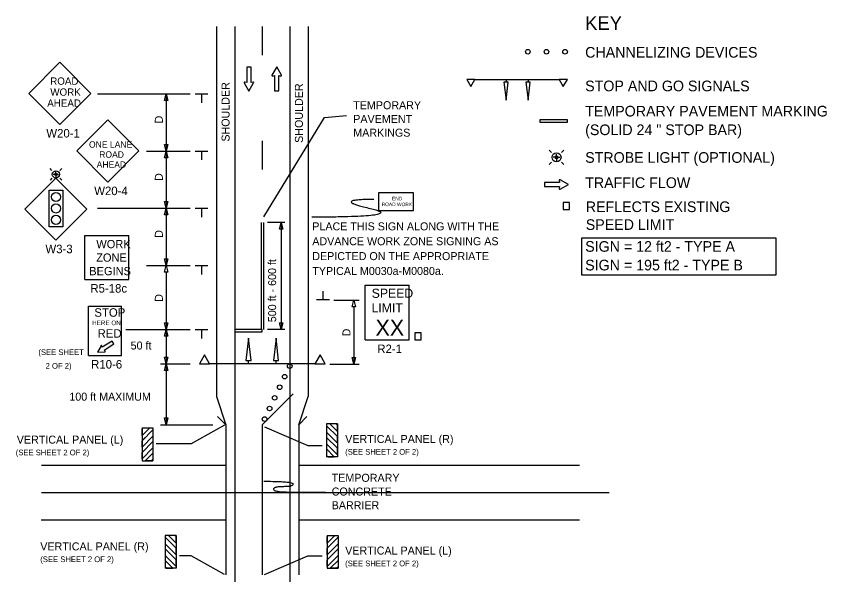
# Model space of a CAD drawing. Extents: x 16733 to 18484, y 7218 to 8208.
# Drawn here: x 16739 to 17447, y 7706 to 8195 of the extents above; entities that cross this region are included whole.
import ezdxf

# ---------------------------------------------------------------- set-up
doc = ezdxf.new("R2010")
doc.units = 0
for name, color, linetype in [('ALI_LEGAL_EX', 7, 'Continuous'), ('MT_SCRATCH_LEVEL_E', 7, 'Continuous'), ('PAVT_EDGE_EX', 7, 'Continuous'), ('TRAFFIC_SIGNS_PR', 7, 'Continuous'), ('TYPICAL_TEXT_DIMEN_EX', 7, 'Continuous'), ('TYPICAL_TEXT_DIMEN_PR', 7, 'Continuous')]:
    doc.layers.add(name, color=color, linetype=linetype)

msp = doc.modelspace()

# ---------------------------------------------------------------- linework, layer by layer
at = {"layer": 'ALI_LEGAL_EX'}
for points in [[(16953.78, 8185.68), (16953.78, 8160.68)], [(16953.78, 8085.68), (16953.78, 8060.68)], [(16952.78, 8014.45), (16952.78, 7920.82)], [(16954.78, 8014.45), (16954.78, 7920.82)]]:
    msp.add_lwpolyline(points, dxfattribs=at)
at = {"layer": 'MT_SCRATCH_LEVEL_E'}
for p, q in [((16943.98, 8150.09), (16940.24, 8150.09)), ((16940.24, 8150.09), (16940.24, 8136.83)), ((16943.98, 8150.09), (16940.24, 8150.09)), ((16940.24, 8150.09), (16940.24, 8136.83)), ((16943.98, 8136.83), (16943.98, 8150.09)), ((16943.98, 8136.83), (16943.98, 8150.09)), ((16966.37, 8150.35), (16962.26, 8143.11)), ((16966.37, 8150.35), (16962.26, 8143.11)), ((16970.52, 8143.11), (16966.37, 8150.35)), ((16970.52, 8143.11), (16966.37, 8150.35)), ((16962.74, 8142.43), (16964.52, 8142.74)), ((16962.74, 8142.43), (16964.52, 8142.74)), ((16964.52, 8142.74), (16964.52, 8129.49)), ((16964.52, 8142.74), (16964.52, 8129.49)), ((16968.26, 8129.49), (16968.26, 8142.74)), ((16968.26, 8142.74), (16970.04, 8142.43)), ((16968.26, 8129.49), (16968.26, 8142.74)), ((16968.26, 8142.74), (16970.04, 8142.43)), ((16937.98, 8136.47), (16942.13, 8129.22)), ((16937.98, 8136.47), (16942.13, 8129.22)), ((16940.24, 8136.83), (16938.46, 8137.15)), ((16940.24, 8136.83), (16938.46, 8137.15)), ((16942.13, 8129.22), (16946.24, 8136.47)), ((16942.13, 8129.22), (16946.24, 8136.47)), ((16945.76, 8137.15), (16943.98, 8136.83)), ((16945.76, 8137.15), (16943.98, 8136.83)), ((16964.52, 8129.49), (16968.26, 8129.49)), ((16964.52, 8129.49), (16968.26, 8129.49)), ((17213.71, 8049.47), (17200.46, 8049.47)), ((17200.46, 8049.47), (17200.46, 8045.73)), ((17213.71, 8049.47), (17200.46, 8049.47)), ((17200.46, 8049.47), (17200.46, 8045.73)), ((17213.4, 8051.25), (17213.71, 8049.47)), ((17213.4, 8051.25), (17213.71, 8049.47)), ((17221.32, 8047.62), (17214.08, 8051.73)), ((17221.32, 8047.62), (17214.08, 8051.73)), ((17200.46, 8045.73), (17213.71, 8045.73)), ((17200.46, 8045.73), (17213.71, 8045.73)), ((17213.71, 8045.73), (17213.4, 8043.95)), ((17213.71, 8045.73), (17213.4, 8043.95)), ((17214.08, 8043.48), (17221.32, 8047.62)), ((17214.08, 8043.48), (17221.32, 8047.62))]:
    msp.add_line(p, q, dxfattribs=at)
for centre, start, end in [((16962.67, 8142.89), 150.42484, 279.96381), ((16962.67, 8142.89), 150.42484, 279.96381), ((16970.11, 8142.89), 260.03619, 29.77312), ((16970.11, 8142.89), 260.03619, 29.77312), ((16938.39, 8136.69), 80.03619, 209.77312), ((16938.39, 8136.69), 80.03619, 209.77312), ((16945.83, 8136.69), 330.42484, 99.96381), ((16945.83, 8136.69), 330.42484, 99.96381), ((17213.86, 8051.33), 60.42484, 189.96381), ((17213.86, 8051.33), 60.42484, 189.96381), ((17213.86, 8043.88), 170.03619, 299.77312), ((17213.86, 8043.88), 170.03619, 299.77312)]:
    msp.add_arc(centre, 0.463, start, end, dxfattribs=at)
at = {"layer": 'PAVT_EDGE_EX'}
for p, q in [((16913.78, 8185.68), (16913.78, 7862.31)), ((16929.78, 8185.68), (16929.78, 7363.75)), ((16977.78, 8185.68), (16977.78, 7363.75)), ((16993.78, 8185.68), (16993.78, 7862.31)), ((16913.78, 7862.31), (16921.78, 7837.6)), ((16953.78, 7837.6), (16980.8, 7864.62)), ((16985.78, 7837.6), (16993.78, 7862.31)), ((16921.78, 7837.6), (16914.71, 7844.68)), ((16985.78, 7837.6), (16992.85, 7844.68)), ((16921.78, 7837.6), (16921.78, 7706.21)), ((16953.78, 7837.6), (16953.78, 7706.21)), ((16985.78, 7837.6), (16985.78, 7706.21)), ((16760.93, 7802.34), (16921.78, 7802.34)), ((16985.78, 7802.34), (17230.97, 7802.34)), ((16760.93, 7778.34), (17256.97, 7778.34)), ((16760.41, 7754.34), (16921.78, 7754.34)), ((16985.78, 7754.34), (17230.97, 7754.34))]:
    msp.add_line(p, q, dxfattribs=at)
for points in [[(16760.93, 7778.34), (16785.93, 7778.34)], [(16860.93, 7778.34), (16885.93, 7778.34)], [(17060.93, 7778.34), (17085.93, 7778.34)], [(17160.93, 7778.34), (17185.93, 7778.34)]]:
    msp.add_lwpolyline(points, dxfattribs=at)
at = {"layer": 'TRAFFIC_SIGNS_PR'}
for p, q in [((16776.85, 8154.4), (16749.69, 8127.25)), ((16804, 8127.25), (16776.85, 8154.4)), ((17139.67, 8139.38), (17213.27, 8139.38)), ((17166.87, 8139.38), (17166.87, 8136.97)), ((17186.07, 8139.38), (17186.07, 8136.97)), ((16749.69, 8127.25), (16776.85, 8100.09)), ((16776.85, 8100.09), (16804, 8127.25)), ((16818.71, 8104.04), (16791.55, 8076.89)), ((16845.86, 8076.89), (16818.71, 8104.04)), ((17206.69, 8075.61), (17204.66, 8077.65)), ((17215.25, 8075.61), (17217.29, 8077.65)), ((16791.55, 8076.89), (16818.71, 8049.73)), ((16818.71, 8049.73), (16845.86, 8076.89)), ((17210.97, 8071.33), (17208.1, 8071.33)), ((17210.97, 8071.33), (17210.97, 8074.21)), ((17210.97, 8071.33), (17210.97, 8067.4)), ((17210.97, 8071.33), (17213.85, 8071.33)), ((17206.69, 8067.05), (17204.66, 8065.02)), ((17217.29, 8065.02), (17215.25, 8067.05)), ((16769.94, 8059.84), (16768.32, 8061.46)), ((16773.37, 8056.41), (16771.07, 8056.41)), ((16773.37, 8056.41), (16773.37, 8058.72)), ((16773.37, 8056.41), (16773.37, 8053.26)), ((16773.37, 8056.41), (16775.67, 8056.41)), ((16776.79, 8059.84), (16778.42, 8061.46)), ((16773.37, 8053.26), (16746.22, 8026.11)), ((16769.94, 8052.99), (16768.32, 8051.36)), ((16800.52, 8026.11), (16773.37, 8053.26)), ((16778.42, 8051.36), (16776.79, 8052.99)), ((16746.22, 8026.11), (16773.37, 7998.96)), ((16773.37, 7998.96), (16800.52, 8026.11)), ((16798.7, 7964.51), (16798.7, 8002.91)), ((16798.7, 8002.91), (16837.1, 8002.91)), ((16837.1, 7964.51), (16837.1, 8002.91)), ((16798.7, 7964.51), (16837.1, 7964.51)), ((17043.66, 7959.64), (17082.06, 7959.64)), ((17043.66, 7911.64), (17043.66, 7959.64)), ((17082.06, 7911.64), (17082.06, 7959.64)), ((16801.79, 7941.3), (16830.59, 7941.3)), ((16801.79, 7898.1), (16801.79, 7941.3)), ((16816.19, 7941.3), (16816.19, 7941.3)), ((16830.59, 7898.1), (16830.59, 7941.3)), ((17043.66, 7911.64), (17082.06, 7911.64)), ((16801.79, 7898.1), (16830.59, 7898.1)), ((16941.78, 7890.82), (16941.78, 7893.84)), ((16965.78, 7890.82), (16965.78, 7893.84)), ((16999.78, 7890.82), (16907.78, 7890.82)), ((17019.53, 7838.39), (17009.93, 7838.39)), ((17009.93, 7838.39), (17009.93, 7809.59)), ((17019.53, 7827.12), (17009.93, 7836.72)), ((17019.53, 7831.64), (17012.78, 7838.39)), ((17019.53, 7837.3), (17018.44, 7838.39)), ((17019.53, 7838.39), (17019.53, 7809.59)), ((16848.65, 7834.79), (16858.25, 7834.79)), ((16848.65, 7834.79), (16848.65, 7805.99)), ((16848.65, 7833.71), (16849.74, 7834.79)), ((16848.65, 7828.05), (16855.4, 7834.79)), ((16848.65, 7823.52), (16858.25, 7833.12)), ((16858.25, 7834.79), (16858.25, 7805.99)), ((17019.53, 7821.46), (17009.93, 7831.06)), ((16848.65, 7817.87), (16858.25, 7827.47)), ((16848.65, 7813.34), (16858.25, 7822.94)), ((16850.07, 7824.94), (16851.48, 7826.35)), ((17019.53, 7816.93), (17009.93, 7826.53)), ((16848.65, 7807.68), (16858.25, 7817.28)), ((17019.53, 7811.28), (17009.93, 7820.88)), ((17016.7, 7809.59), (17009.93, 7816.35)), ((16851.49, 7805.99), (16858.25, 7812.76)), ((17011.04, 7809.59), (17009.93, 7810.69)), ((17019.53, 7809.59), (17009.93, 7809.59)), ((16848.65, 7805.99), (16858.25, 7805.99)), ((16857.15, 7805.99), (16858.25, 7807.1)), ((16878.5, 7740.81), (16868.9, 7740.81)), ((16868.9, 7740.81), (16868.9, 7712.01)), ((16878.5, 7729.54), (16868.9, 7739.14)), ((16878.5, 7734.06), (16871.76, 7740.81)), ((16878.5, 7739.72), (16877.41, 7740.81)), ((16878.5, 7740.81), (16878.5, 7712.01)), ((17010.4, 7740.81), (17020, 7740.81)), ((17010.4, 7740.81), (17010.4, 7712.01)), ((17010.4, 7739.72), (17011.49, 7740.81)), ((17010.4, 7734.06), (17017.15, 7740.81)), ((17010.4, 7729.54), (17020, 7739.14)), ((17020, 7740.81), (17020, 7712.01)), ((16878.5, 7723.88), (16868.9, 7733.48)), ((17010.4, 7723.88), (17020, 7733.48)), ((17011.81, 7730.95), (17013.23, 7732.36)), ((16878.5, 7719.35), (16868.9, 7728.95)), ((16878.5, 7713.7), (16868.9, 7723.3)), ((17010.4, 7719.35), (17020, 7728.95)), ((17010.4, 7713.7), (17020, 7723.3)), ((16875.67, 7712.01), (16868.9, 7718.77)), ((17013.24, 7712.01), (17020, 7718.77)), ((16870.01, 7712.01), (16868.9, 7713.11)), ((16878.5, 7712.01), (16868.9, 7712.01)), ((17010.4, 7712.01), (17020, 7712.01)), ((17018.89, 7712.01), (17020, 7713.11))]:
    msp.add_line(p, q, dxfattribs=at)
for points in [[(17132.47, 8139.38), (17136.07, 8133.15), (17139.67, 8139.38)], [(17165.07, 8136.97), (17166.87, 8121.43), (17168.67, 8136.97)], [(17184.27, 8136.97), (17186.07, 8121.43), (17187.87, 8136.97)], [(17213.27, 8139.38), (17216.87, 8133.15), (17220.47, 8139.38)], [(17196.47, 8104.19), (17196.47, 8102.19), (17220.47, 8102.19), (17220.47, 8104.19)], [(16779.43, 8010.65), (16767.43, 8010.65), (16767.43, 8042.65), (16779.43, 8042.65)], [(17055.24, 8024.86), (17085.96, 8024.86), (17085.96, 8040.22), (17055.24, 8040.22)], [(17216.69, 8025.68), (17222.29, 8025.68), (17222.29, 8031.85), (17216.69, 8031.85)], [(16929.78, 7920.82), (16929.78, 7918.82), (16953.78, 7918.82), (16953.78, 7920.82)], [(17087.07, 7911.64), (17092.67, 7911.64), (17092.67, 7917.81), (17087.07, 7917.81)], [(16944.03, 7893.84), (16941.78, 7913.26), (16939.53, 7893.84)], [(16968.03, 7893.84), (16965.78, 7913.26), (16963.53, 7893.84)], [(16907.78, 7890.82), (16903.28, 7898.62), (16898.78, 7890.82)], [(17008.78, 7890.82), (17004.28, 7898.62), (16999.78, 7890.82)], [(17019.53, 7827.12), (17009.93, 7836.72), (17009.93, 7831.06), (17019.53, 7821.46)], [(17018.44, 7838.39), (17012.78, 7838.39), (17019.53, 7831.64), (17019.53, 7837.3)], [(16849.74, 7834.79), (16855.4, 7834.79), (16848.65, 7828.05), (16848.65, 7833.71)], [(16848.65, 7823.52), (16858.25, 7833.12), (16858.25, 7827.47), (16848.65, 7817.87)], [(16848.65, 7813.34), (16858.25, 7822.94), (16858.25, 7817.28), (16848.65, 7807.68)], [(17019.53, 7816.93), (17009.93, 7826.53), (17009.93, 7820.88), (17019.53, 7811.28)], [(17009.93, 7816.35), (17009.93, 7810.69), (17011.04, 7809.59), (17016.7, 7809.59)], [(16858.25, 7812.76), (16858.25, 7807.1), (16857.15, 7805.99), (16851.49, 7805.99)], [(16878.5, 7729.54), (16868.9, 7739.14), (16868.9, 7733.48), (16878.5, 7723.88)], [(16877.41, 7740.81), (16871.76, 7740.81), (16878.5, 7734.06), (16878.5, 7739.72)], [(17011.49, 7740.81), (17017.15, 7740.81), (17010.4, 7734.06), (17010.4, 7739.72)], [(17010.4, 7729.54), (17020, 7739.14), (17020, 7733.48), (17010.4, 7723.88)], [(16878.5, 7719.35), (16868.9, 7728.95), (16868.9, 7723.3), (16878.5, 7713.7)], [(17010.4, 7719.35), (17020, 7728.95), (17020, 7723.3), (17010.4, 7713.7)], [(16868.9, 7718.77), (16868.9, 7713.11), (16870.01, 7712.01), (16875.67, 7712.01)], [(17020, 7718.77), (17020, 7713.11), (17018.89, 7712.01), (17013.24, 7712.01)]]:
    msp.add_lwpolyline(points, close=True, dxfattribs=at)
for points in [[(16816.39, 7901.75), (16815.47, 7902.78), (16824.12, 7908.14), (16822.61, 7910.59), (16813.95, 7905.23), (16813.44, 7906.51)], [(16812.8, 7906.55), (16809.75, 7900.92), (16816.14, 7901.16)]]:
    msp.add_lwpolyline(points, dxfattribs=at)
for centre, radius in [((17185.87, 8163.66), 2), ((17202.17, 8163.66), 2), ((17218.47, 8163.66), 2), ((17210.97, 8071.33), 3.94), ((17210.97, 8071.33), 1.28), ((16773.37, 8056.41), 3.15), ((16773.37, 8056.41), 1.02), ((16773.43, 8036.65), 4), ((16773.43, 8026.65), 4), ((16773.43, 8016.65), 4), ((16977.78, 7888.82), 2), ((16973.38, 7879.55), 2), ((16968.98, 7870.29), 2), ((16964.58, 7861.03), 2), ((16960.18, 7851.76), 2), ((16955.78, 7842.5), 2)]:
    msp.add_circle(centre, radius, dxfattribs=at)
for centre, radius, start, end in [((16813.11, 7906.38), 0.355, 21.71521, 151.42661), ((16816.13, 7901.51), 0.354, 272.17868, 41.91782)]:
    msp.add_arc(centre, radius, start, end, dxfattribs=at)
msp.add_open_spline([(17051.39, 8034.49), (17013.6, 8034.49), (17081.62, 8019.01), (16997.05, 8019.01)], degree=2, dxfattribs=at)
at = {"layer": 'TYPICAL_TEXT_DIMEN_EX'}
msp.add_lwpolyline([(17232.99, 8000.99), (17402.65, 8000.99), (17402.65, 7968.45), (17232.99, 7968.45)], close=True, dxfattribs=at)
at = {"layer": 'TYPICAL_TEXT_DIMEN_PR'}
for p, q in [((16809.81, 8126.79), (16890.78, 8126.79)), ((16868.21, 8120.93), (16869.78, 8126.79)), ((16869.78, 8120.93), (16868.21, 8120.93)), ((16869.78, 8126.79), (16869.78, 8076.79)), ((16869.78, 8126.79), (16871.35, 8120.93)), ((16871.35, 8120.93), (16869.78, 8120.93)), ((16895.03, 8126.79), (16906.28, 8126.79)), ((16900.66, 8126.79), (16900.66, 8119)), ((16955.03, 8019.28), (17008.12, 8106.22)), ((17008.12, 8106.22), (17027.42, 8108.04)), ((16869.78, 8076.79), (16868.21, 8082.65)), ((16868.21, 8082.65), (16869.78, 8082.65)), ((16869.78, 8076.79), (16868.21, 8082.65)), ((16868.21, 8082.65), (16869.78, 8082.65)), ((16869.78, 8082.65), (16871.35, 8082.65)), ((16871.35, 8082.65), (16869.78, 8076.79)), ((16869.78, 8082.65), (16871.35, 8082.65)), ((16871.35, 8082.65), (16869.78, 8076.79)), ((16852.48, 8076.79), (16890.78, 8076.79)), ((16868.21, 8070.93), (16869.78, 8076.79)), ((16869.78, 8070.93), (16868.21, 8070.93)), ((16869.78, 8076.79), (16869.78, 8026.79)), ((16869.78, 8076.79), (16871.35, 8070.93)), ((16871.35, 8070.93), (16869.78, 8070.93)), ((16895.03, 8076.79), (16906.28, 8076.79)), ((16900.66, 8076.79), (16900.66, 8069)), ((16869.78, 8026.79), (16868.21, 8032.65)), ((16868.21, 8032.65), (16869.78, 8032.65)), ((16869.78, 8032.65), (16871.35, 8032.65)), ((16871.35, 8032.65), (16869.78, 8026.79)), ((16809.81, 8026.79), (16890.78, 8026.79)), ((16868.21, 8020.93), (16869.78, 8026.79)), ((16869.78, 8020.93), (16868.21, 8020.93)), ((16869.78, 8026.79), (16871.35, 8020.93)), ((16869.78, 8026.79), (16869.78, 7976.79)), ((16871.35, 8020.93), (16869.78, 8020.93)), ((16895.03, 8026.79), (16906.28, 8026.79)), ((16900.66, 8026.79), (16900.66, 8019)), ((16973.59, 8014.45), (16958.31, 8014.45)), ((16968.72, 8008.59), (16970.29, 8014.45)), ((16970.29, 8014.45), (16970.29, 7920.82)), ((16970.29, 8014.45), (16971.86, 8008.59)), ((16970.29, 8008.59), (16968.72, 8008.59)), ((16971.86, 8008.59), (16970.29, 8008.59)), ((16869.78, 7976.79), (16868.21, 7982.65)), ((16868.21, 7982.65), (16869.78, 7982.65)), ((16869.78, 7982.65), (16871.35, 7982.65)), ((16871.35, 7982.65), (16869.78, 7976.79)), ((16852.48, 7976.79), (16890.78, 7976.79)), ((16868.21, 7970.93), (16869.78, 7976.79)), ((16869.78, 7976.79), (16871.35, 7970.93)), ((16895.03, 7976.79), (16906.28, 7976.79)), ((16900.66, 7976.79), (16900.66, 7969)), ((16869.78, 7970.93), (16868.21, 7970.93)), ((16871.35, 7970.93), (16869.78, 7970.93)), ((16869.78, 7970.82), (16869.78, 7920.82)), ((17006.91, 7946.63), (17006.91, 7954.42)), ((17012.53, 7946.63), (17001.28, 7946.63)), ((17016.27, 7946.56), (17038.58, 7946.56)), ((17032.21, 7940.7), (17033.78, 7946.56)), ((17033.78, 7946.56), (17035.35, 7940.7)), ((17033.78, 7940.7), (17032.21, 7940.7)), ((17035.35, 7940.7), (17033.78, 7940.7)), ((17033.78, 7940.6), (17033.78, 7890.6)), ((16869.78, 7920.82), (16868.21, 7926.68)), ((16868.21, 7926.68), (16869.78, 7926.68)), ((16869.78, 7926.68), (16871.35, 7926.68)), ((16871.35, 7926.68), (16869.78, 7920.82)), ((16970.29, 7920.82), (16968.72, 7926.68)), ((16968.72, 7926.68), (16970.29, 7926.68)), ((16970.29, 7926.68), (16971.86, 7926.68)), ((16971.86, 7926.68), (16970.29, 7920.82)), ((16834.5, 7920.82), (16890.78, 7920.82)), ((16868.21, 7914.96), (16869.78, 7920.82)), ((16869.78, 7914.96), (16868.21, 7914.96)), ((16869.78, 7920.82), (16869.78, 7890.82)), ((16869.78, 7920.82), (16871.35, 7914.96)), ((16871.35, 7914.96), (16869.78, 7914.96)), ((16895.03, 7920.82), (16906.28, 7920.82)), ((16900.66, 7920.82), (16900.66, 7913.04)), ((16973.59, 7920.82), (16958.31, 7920.82)), ((16869.78, 7890.82), (16868.21, 7896.68)), ((16868.21, 7896.68), (16869.78, 7896.68)), ((16869.78, 7896.68), (16871.35, 7896.68)), ((16871.35, 7896.68), (16869.78, 7890.82)), ((17033.78, 7890.6), (17032.21, 7896.46)), ((17032.21, 7896.46), (17033.78, 7896.46)), ((17033.78, 7896.46), (17035.35, 7896.46)), ((17035.35, 7896.46), (17033.78, 7890.6)), ((16864.78, 7890.82), (16890.78, 7890.82)), ((16868.21, 7884.96), (16869.78, 7890.82)), ((16869.78, 7890.82), (16871.35, 7884.96)), ((16869.78, 7890.82), (16869.78, 7837.6)), ((17012.95, 7890.6), (17038.58, 7890.6)), ((16869.78, 7884.96), (16868.21, 7884.96)), ((16871.35, 7884.96), (16869.78, 7884.96)), ((16864.78, 7837.6), (16910.48, 7837.6)), ((16869.78, 7837.6), (16868.21, 7843.47)), ((16868.21, 7843.47), (16869.78, 7843.47)), ((16869.78, 7843.47), (16871.35, 7843.47)), ((16871.35, 7843.47), (16869.78, 7837.6)), ((16920.82, 7837.05), (16891.56, 7820.82)), ((16955.78, 7835.85), (16993.57, 7819.41)), ((16891.56, 7820.82), (16860.98, 7820.82)), ((16993.57, 7819.41), (17006.03, 7819.41)), ((16891.56, 7722.81), (16881.31, 7722.81)), ((16920.82, 7706.58), (16891.56, 7722.81)), ((16955.78, 7706.5), (16993.57, 7722.95)), ((16993.57, 7722.95), (17006.03, 7722.95))]:
    msp.add_line(p, q, dxfattribs=at)
msp.add_open_spline([(16955.22, 7788.11), (16980.8, 7788.11), (16980.8, 7783.4), (16963.59, 7783.4), (16963.59, 7778.69), (16996.58, 7778.69), (17009.05, 7778.69)], degree=2, dxfattribs=at)

# ---------------------------------------------------------------- texts
at = {"layer": 'TRAFFIC_SIGNS_PR'}
for s, height, p in [('ROAD', 6.4, (16768.39, 8134.78)), ('WORK', 6.4, (16768.5, 8125.18)), ('AHEAD', 6.4, (16765.81, 8115.58)), ('W20-1', 7.44, (16765.01, 8088.65)), ('ONE LANE', 5.6, (16802.29, 8079.76)), ('ROAD', 5.6, (16811.24, 8070.96)), ('AHEAD', 5.6, (16809, 8062.16)), ('W20-4', 7.44, (16806.89, 8038.29)), ('END', 3.065, (17067.24, 8033.76)), ('ROAD WORK', 3.065, (17058.13, 8028.65)), ('PLACE THIS SIGN ALONG WITH THE', 7, (16997.49, 8007.48)), ('ADVANCE WORK ZONE SIGNING AS', 7, (16997.49, 7994.48)), ('W3-3', 7.44, (16764.24, 7987.52)), ('WORK', 7.217, (16808.7, 7991.88)), ('ZONE', 7.217, (16808.58, 7980.07)), ('DEPICTED ON THE APPROPRIATE', 7, (16997.49, 7981.48)), ('BEGINS', 7.217, (16802.51, 7968.26)), ('TYPICAL M0030a-M0080a.', 7, (16997.49, 7968.48)), ('R5-18c', 7.44, (16803.51, 7953.07)), ('SPEED', 8, (17049.42, 7948.5)), ('LIMIT', 8, (17049.26, 7935.7)), ('STOP', 7.44, (16806.99, 7931.96)), ('HERE ON', 4, (16804.99, 7924.6)), ('XX', 14.031, (17052.77, 7915.4)), ('RED', 7.44, (16809.8, 7913.65)), ('R2-1', 7.44, (17054.33, 7900.2)), ('R10-6', 7.44, (16804.17, 7886.66))]:
    msp.add_text(s, height=height, dxfattribs=at).set_placement(p)
at = {"layer": 'TYPICAL_TEXT_DIMEN_EX'}
for s, height, p in [('KEY', 12, (17236.02, 8182.71)), ('CHANNELIZING DEVICES', 9.3, (17236.02, 8158.5)), ('STOP AND GO SIGNALS', 9.3, (17236.02, 8129.1)), ('TEMPORARY PAVEMENT MARKING', 9.3, (17236.02, 8107.05)), ('(SOLID 24 " STOP BAR)', 9.3, (17236.02, 8090.75)), ('STROBE LIGHT (OPTIONAL)', 9.3, (17236.02, 8066.55)), ('TRAFFIC FLOW', 9.3, (17236.02, 8044.5)), ('REFLECTS EXISTING', 9.3, (17236.52, 8023.48)), ('SPEED LIMIT', 9.3, (17236.52, 8007.88)), ('SIGN = 12 ft2 - TYPE A', 9.3, (17236.02, 7988.77)), ('SIGN = 195 ft2 - TYPE B', 9.3, (17236.02, 7972.47))]:
    msp.add_text(s, height=height, dxfattribs=at).set_placement(p)
at = {"layer": 'TYPICAL_TEXT_DIMEN_PR'}
for s, p in [('SHOULDER', (16925.2, 8085.06)), ('SHOULDER', (16989.31, 8083.98)), ('D', (16866.85, 8101.01)), ('D', (16866.85, 8050.67)), ('D', (16866.85, 8001.01)), ('500 ft - 600 ft', (16965.89, 7927.19)), ('D', (16866.85, 7945.04)), ('D', (17030.85, 7914.81))]:
    msp.add_text(s, height=7, rotation=90, dxfattribs=at).set_placement(p)
for s, height, p in [('TEMPORARY', 7, (17033.3, 8113.38)), ('PAVEMENT', 7, (17033.3, 8101.38)), ('MARKINGS', 7, (17033.3, 8089.38)), ('50 ft', 7, (16838.71, 7903.29)), ('(SEE SHEET', 5, (16758.05, 7898.49)), ('2 OF 2)', 5, (16764.38, 7886.49)), ('100 ft MAXIMUM', 7, (16785.14, 7858.6)), ('VERTICAL PANEL (L)', 7, (16739.16, 7821.03)), ('VERTICAL PANEL (R)', 7, (17026.27, 7821.59)), ('(SEE SHEET 2 OF 2)', 5, (16738.27, 7810.78)), ('(SEE SHEET 2 OF 2)', 5, (17026.27, 7811.34)), ('TEMPORARY', 7, (17014.45, 7787.65)), ('CONCRETE', 7, (17014.45, 7775.65)), ('BARRIER', 7, (17014.45, 7763.65)), ('VERTICAL PANEL (R)', 7, (16759.71, 7727.68)), ('VERTICAL PANEL (L)', 7, (17026.25, 7724.04)), ('(SEE SHEET 2 OF 2)', 5, (16759.71, 7717.43)), ('(SEE SHEET 2 OF 2)', 5, (17026.25, 7713.79))]:
    msp.add_text(s, height=height, dxfattribs=at).set_placement(p)

doc.saveas('drawing.dxf')
